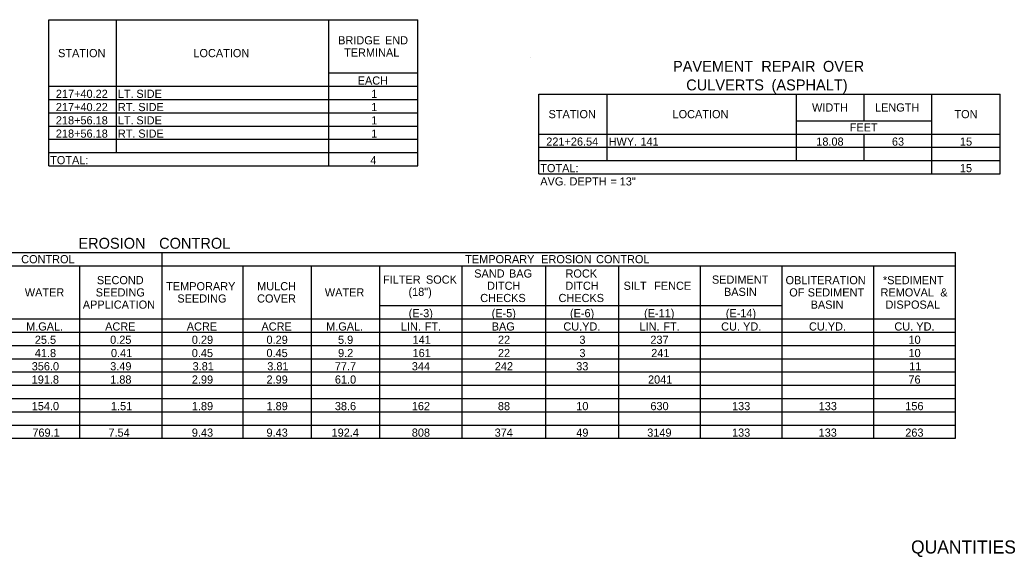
# Model space of a CAD drawing. Extents: x 1334738 to 1334853, y 402732 to 402753.
# Drawn here: x 1334792.08 to 1334810.35, y 402732.57 to 402742.44 of the extents above; entities that cross this region are included whole.
import ezdxf

# ---------------------------------------------------------------- set-up
doc = ezdxf.new("R2010")
doc.units = 0
doc.layers.add('Default', color=7, linetype='Continuous')
doc.layers.add('R_No Plot', color=7, linetype='Continuous')

msp = doc.modelspace()

# ---------------------------------------------------------------- linework, layer by layer
at = {"layer": 'Default'}
for p, q in [((1334792.606, 402742.441), (1334799.383, 402742.441)), ((1334792.606, 402739.76), (1334792.606, 402742.441)), ((1334792.606, 402739.76), (1334792.606, 402742.441)), ((1334793.85, 402740.003), (1334793.85, 402742.441)), ((1334797.75, 402739.76), (1334797.75, 402742.441)), ((1334799.383, 402739.76), (1334799.383, 402742.441)), ((1334801.459, 402741.758), (1334801.459, 402741.758)), ((1334797.75, 402741.466), (1334799.383, 402741.466)), ((1334797.75, 402739.76), (1334797.75, 402741.466)), ((1334792.606, 402741.222), (1334799.383, 402741.222)), ((1334793.85, 402740.003), (1334793.85, 402741.222)), ((1334799.383, 402740.247), (1334799.383, 402741.222)), ((1334801.605, 402741.075), (1334810.076, 402741.075)), ((1334801.605, 402739.613), (1334801.605, 402741.075)), ((1334801.605, 402739.613), (1334801.605, 402741.075)), ((1334802.861, 402739.857), (1334802.861, 402741.075)), ((1334806.334, 402739.857), (1334806.334, 402741.075)), ((1334807.577, 402740.588), (1334807.577, 402741.075)), ((1334808.82, 402739.613), (1334808.82, 402741.075)), ((1334810.076, 402739.613), (1334810.076, 402741.075)), ((1334810.076, 402739.613), (1334810.076, 402741.075)), ((1334792.606, 402740.978), (1334799.383, 402740.978)), ((1334792.606, 402740.735), (1334799.383, 402740.735)), ((1334806.334, 402740.588), (1334808.82, 402740.588)), ((1334806.334, 402740.588), (1334808.82, 402740.588)), ((1334792.606, 402740.491), (1334799.383, 402740.491)), ((1334801.605, 402740.344), (1334810.076, 402740.344)), ((1334802.861, 402739.857), (1334802.861, 402740.344)), ((1334806.334, 402739.857), (1334806.334, 402740.344)), ((1334807.577, 402739.857), (1334807.577, 402740.344)), ((1334807.577, 402739.857), (1334807.577, 402740.344)), ((1334808.82, 402740.344), (1334810.076, 402740.344)), ((1334808.82, 402739.857), (1334808.82, 402740.344)), ((1334792.606, 402740.247), (1334799.383, 402740.247)), ((1334792.606, 402740.003), (1334799.383, 402740.003)), ((1334801.605, 402740.1), (1334810.076, 402740.1)), ((1334801.605, 402739.857), (1334810.076, 402739.857)), ((1334806.334, 402739.857), (1334807.577, 402739.857)), ((1334807.577, 402739.857), (1334808.82, 402739.857)), ((1334808.82, 402739.857), (1334810.076, 402739.857)), ((1334792.606, 402739.76), (1334799.383, 402739.76)), ((1334801.605, 402739.613), (1334810.076, 402739.613)), ((1334780.063, 402738.166), (1334809.252, 402738.166)), ((1334794.688, 402737.923), (1334794.688, 402738.166)), ((1334794.688, 402734.754), (1334794.688, 402738.166)), ((1334809.252, 402734.754), (1334809.252, 402738.166)), ((1334788.155, 402737.923), (1334809.252, 402737.923)), ((1334793.176, 402734.754), (1334793.176, 402737.923)), ((1334796.174, 402734.754), (1334796.174, 402737.923)), ((1334797.43, 402734.754), (1334797.43, 402737.923)), ((1334798.685, 402734.754), (1334798.685, 402737.923)), ((1334800.196, 402734.754), (1334800.196, 402737.923)), ((1334801.732, 402734.754), (1334801.732, 402737.923)), ((1334803.073, 402734.754), (1334803.073, 402737.923)), ((1334804.572, 402734.754), (1334804.572, 402737.923)), ((1334806.071, 402734.754), (1334806.071, 402737.923)), ((1334807.753, 402734.754), (1334807.753, 402737.923)), ((1334798.685, 402737.191), (1334806.071, 402737.191)), ((1334788.155, 402736.948), (1334809.252, 402736.948)), ((1334793.176, 402734.998), (1334793.176, 402736.948)), ((1334794.688, 402734.998), (1334794.688, 402736.948)), ((1334796.174, 402734.754), (1334796.174, 402736.948)), ((1334797.43, 402734.754), (1334797.43, 402736.948)), ((1334798.685, 402734.998), (1334798.685, 402736.948)), ((1334800.196, 402734.754), (1334800.196, 402736.948)), ((1334801.732, 402734.998), (1334801.732, 402736.948)), ((1334803.073, 402734.998), (1334803.073, 402736.948)), ((1334804.572, 402734.754), (1334804.572, 402736.948)), ((1334806.071, 402736.948), (1334809.252, 402736.948)), ((1334806.071, 402734.754), (1334806.071, 402736.948)), ((1334807.753, 402734.754), (1334807.753, 402736.948)), ((1334780.063, 402736.704), (1334809.252, 402736.704)), ((1334809.252, 402734.998), (1334809.252, 402736.704)), ((1334780.063, 402736.46), (1334809.252, 402736.46)), ((1334780.063, 402736.216), (1334809.252, 402736.216)), ((1334780.063, 402735.973), (1334809.252, 402735.973)), ((1334780.063, 402735.729), (1334809.252, 402735.729)), ((1334780.063, 402735.485), (1334809.252, 402735.485)), ((1334780.063, 402735.241), (1334809.252, 402735.241)), ((1334780.063, 402734.998), (1334809.252, 402734.998)), ((1334789.41, 402734.998), (1334794.688, 402734.998)), ((1334794.688, 402734.998), (1334796.174, 402734.998)), ((1334796.174, 402734.998), (1334798.685, 402734.998)), ((1334798.685, 402734.998), (1334800.196, 402734.998)), ((1334800.196, 402734.998), (1334803.073, 402734.998)), ((1334803.073, 402734.998), (1334807.753, 402734.998)), ((1334807.753, 402734.998), (1334809.252, 402734.998)), ((1334780.063, 402734.754), (1334809.252, 402734.754))]:
    msp.add_line(p, q, dxfattribs=at)

# ---------------------------------------------------------------- texts
for s, height, p in [('BRIDGE', 0.15, (1334797.919, 402741.991)), (' END', 0.15, (1334798.723, 402741.991)), ('STATION', 0.15, (1334792.776, 402741.756)), ('LOCATION', 0.15, (1334795.261, 402741.756)), ('TERMINAL', 0.15, (1334798.028, 402741.766)), ('PAVEMENT', 0.2, (1334804.067, 402741.487)), (' REPAIR', 0.2, (1334805.614, 402741.487)), (' OVER', 0.2, (1334806.746, 402741.487)), ('EACH', 0.15, (1334798.277, 402741.252)), ('CULVERTS', 0.2, (1334804.31, 402741.146)), (' (ASPHALT)', 0.2, (1334805.802, 402741.146)), ('217+40.22', 0.15, (1334792.735, 402741.008)), ('LT.', 0.15, (1334793.874, 402741.008)), (' SIDE', 0.15, (1334794.158, 402741.008)), ('1', 0.15, (1334798.527, 402741.008)), ('217+40.22', 0.15, (1334792.735, 402740.765)), ('RT.', 0.15, (1334793.874, 402740.765)), (' SIDE', 0.15, (1334794.193, 402740.765)), ('1', 0.15, (1334798.527, 402740.765)), ('WIDTH', 0.15, (1334806.62, 402740.757)), ('LENGTH', 0.15, (1334807.776, 402740.757)), ('STATION', 0.15, (1334801.782, 402740.635)), ('LOCATION', 0.15, (1334804.059, 402740.635)), ('TON', 0.15, (1334809.235, 402740.635)), ('218+56.18', 0.15, (1334792.735, 402740.521)), ('LT.', 0.15, (1334793.874, 402740.521)), (' SIDE', 0.15, (1334794.158, 402740.521)), ('1', 0.15, (1334798.527, 402740.521)), ('FEET', 0.15, (1334807.312, 402740.391)), ('218+56.18', 0.15, (1334792.735, 402740.277)), ('RT.', 0.15, (1334793.874, 402740.277)), (' SIDE', 0.15, (1334794.193, 402740.277)), ('1', 0.15, (1334798.527, 402740.277)), ('221+26.54', 0.15, (1334801.74, 402740.13)), ('HWY.', 0.15, (1334802.885, 402740.13)), (' 141', 0.15, (1334803.414, 402740.13)), ('18.08', 0.15, (1334806.698, 402740.13)), ('63', 0.15, (1334808.087, 402740.13)), ('15', 0.15, (1334809.336, 402740.13)), ('TOTAL:', 0.15, (1334792.631, 402739.79)), ('4', 0.15, (1334798.51, 402739.79)), ('TOTAL:', 0.15, (1334801.63, 402739.643)), ('15', 0.15, (1334809.335, 402739.643)), ('AVG.', 0.15, (1334801.63, 402739.399)), (' DEPTH', 0.15, (1334802.112, 402739.399)), (' =', 0.15, (1334802.864, 402739.399)), (' 13"', 0.15, (1334803.033, 402739.399)), ('EROSION', 0.2, (1334793.149, 402738.237)), (' CONTROL', 0.2, (1334794.557, 402738.237)), (' CONTROL', 0.15, (1334792.043, 402737.97)), ('TEMPORARY', 0.15, (1334800.252, 402737.97)), (' EROSION', 0.15, (1334801.591, 402737.97)), (' CONTROL', 0.15, (1334802.599, 402737.97)), ('SAND', 0.15, (1334800.417, 402737.707)), (' BAG', 0.15, (1334801, 402737.707)), ('ROCK', 0.15, (1334802.094, 402737.707)), ('SECOND', 0.15, (1334793.489, 402737.585)), ('TEMPORARY', 0.15, (1334794.761, 402737.473)), ('MULCH', 0.15, (1334796.432, 402737.473)), ('FILTER', 0.15, (1334798.743, 402737.595)), (' SOCK', 0.15, (1334799.475, 402737.595)), ('DITCH', 0.15, (1334800.652, 402737.482)), ('DITCH', 0.15, (1334802.09, 402737.482)), ('SILT', 0.15, (1334803.16, 402737.482)), ('  FENCE', 0.15, (1334803.61, 402737.482)), ('SEDIMENT', 0.15, (1334804.782, 402737.595)), ('OBLITERATION', 0.15, (1334806.134, 402737.585)), ('*SEDIMENT', 0.15, (1334807.922, 402737.585)), ('WATER', 0.15, (1334792.165, 402737.36)), ('SEEDING', 0.15, (1334793.467, 402737.36)), ('SEEDING', 0.15, (1334794.966, 402737.248)), ('COVER', 0.15, (1334796.43, 402737.248)), ('WATER', 0.15, (1334797.674, 402737.36)), ('(18")', 0.15, (1334799.21, 402737.37)), ('CHECKS', 0.15, (1334800.527, 402737.257)), ('CHECKS', 0.15, (1334801.965, 402737.257)), ('BASIN', 0.15, (1334805.003, 402737.37)), ('OF', 0.15, (1334806.202, 402737.36)), (' SEDIMENT', 0.15, (1334806.484, 402737.36)), ('REMOVAL', 0.15, (1334807.878, 402737.36)), (' &', 0.15, (1334808.92, 402737.36)), ('APPLICATION', 0.15, (1334793.23, 402737.135)), ('BASIN', 0.15, (1334806.594, 402737.135)), ('DISPOSAL', 0.15, (1334807.969, 402737.135)), ('(E-3)', 0.15, (1334799.213, 402736.978)), ('(E-5)', 0.15, (1334800.737, 402736.978)), ('(E-6)', 0.15, (1334802.175, 402736.978)), ('(E-11)', 0.15, (1334803.536, 402736.978)), ('(E-14)', 0.15, (1334805.036, 402736.978)), ('M.GAL.', 0.15, (1334792.189, 402736.734)), ('ACRE', 0.15, (1334793.64, 402736.734)), ('ACRE', 0.15, (1334795.139, 402736.734)), ('ACRE', 0.15, (1334796.51, 402736.734)), ('M.GAL.', 0.15, (1334797.698, 402736.734)), ('LIN.', 0.15, (1334799.071, 402736.734)), (' FT.', 0.15, (1334799.452, 402736.734)), ('BAG', 0.15, (1334800.738, 402736.734)), ('CU.YD.', 0.15, (1334802.054, 402736.734)), ('LIN.', 0.15, (1334803.452, 402736.734)), (' FT.', 0.15, (1334803.834, 402736.734)), ('CU.', 0.15, (1334804.951, 402736.734)), (' YD.', 0.15, (1334805.298, 402736.734)), ('CU.YD.', 0.15, (1334806.564, 402736.734)), ('CU.', 0.15, (1334808.132, 402736.734)), (' YD.', 0.15, (1334808.479, 402736.734)), ('25.5', 0.15, (1334792.349, 402736.49)), ('0.25', 0.15, (1334793.732, 402736.49)), ('0.29', 0.15, (1334795.232, 402736.49)), ('0.29', 0.15, (1334796.603, 402736.49)), ('5.9', 0.15, (1334797.916, 402736.49)), ('141', 0.15, (1334799.285, 402736.49)), ('22', 0.15, (1334800.853, 402736.49)), ('3', 0.15, (1334802.349, 402736.49)), ('237', 0.15, (1334803.652, 402736.49)), ('10', 0.15, (1334808.391, 402736.49)), ('41.8', 0.15, (1334792.349, 402736.246)), ('0.41', 0.15, (1334793.747, 402736.246)), ('0.45', 0.15, (1334795.231, 402736.246)), ('0.45', 0.15, (1334796.602, 402736.246)), ('9.2', 0.15, (1334797.917, 402736.246)), ('161', 0.15, (1334799.285, 402736.246)), ('22', 0.15, (1334800.853, 402736.246)), ('3', 0.15, (1334802.349, 402736.246)), ('241', 0.15, (1334803.667, 402736.246)), ('10', 0.15, (1334808.391, 402736.246)), ('356.0', 0.15, (1334792.292, 402736.003)), ('3.49', 0.15, (1334793.733, 402736.003)), ('3.81', 0.15, (1334795.246, 402736.003)), ('3.81', 0.15, (1334796.617, 402736.003)), ('77.7', 0.15, (1334797.858, 402736.003)), ('344', 0.15, (1334799.271, 402736.003)), ('242', 0.15, (1334800.795, 402736.003)), ('33', 0.15, (1334802.29, 402736.003)), ('11', 0.15, (1334808.405, 402736.003)), ('191.8', 0.15, (1334792.291, 402735.759)), ('1.88', 0.15, (1334793.733, 402735.759)), ('2.99', 0.15, (1334795.232, 402735.759)), ('2.99', 0.15, (1334796.603, 402735.759)), ('61.0', 0.15, (1334797.859, 402735.759)), ('2041', 0.15, (1334803.608, 402735.759)), ('76', 0.15, (1334808.39, 402735.759)), ('154.0', 0.15, (1334792.292, 402735.271)), ('1.51', 0.15, (1334793.747, 402735.271)), ('1.89', 0.15, (1334795.232, 402735.271)), ('1.89', 0.15, (1334796.603, 402735.271)), ('38.6', 0.15, (1334797.858, 402735.271)), ('162', 0.15, (1334799.271, 402735.271)), ('88', 0.15, (1334800.852, 402735.271)), ('10', 0.15, (1334802.291, 402735.271)), ('630', 0.15, (1334803.652, 402735.271)), ('133', 0.15, (1334805.151, 402735.271)), ('133', 0.15, (1334806.742, 402735.271)), ('156', 0.15, (1334808.332, 402735.271)), ('769.1', 0.15, (1334792.304, 402734.784)), ('7.54', 0.15, (1334793.701, 402734.784)), ('9.43', 0.15, (1334795.232, 402734.784)), ('9.43', 0.15, (1334796.603, 402734.784)), ('192.4', 0.15, (1334797.798, 402734.784)), ('808', 0.15, (1334799.271, 402734.784)), ('374', 0.15, (1334800.792, 402734.784)), ('49', 0.15, (1334802.291, 402734.784)), ('3149', 0.15, (1334803.594, 402734.784)), ('133', 0.15, (1334805.151, 402734.784)), ('133', 0.15, (1334806.741, 402734.784)), ('263', 0.15, (1334808.332, 402734.784))]:
    msp.add_text(s, height=height, dxfattribs=at).set_placement(p)
at = {"layer": 'R_No Plot'}
msp.add_text('QUANTITIES', height=0.24, dxfattribs=at).set_placement((1334808.438, 402732.638))

doc.saveas('drawing.dxf')
